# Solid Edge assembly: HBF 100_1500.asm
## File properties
Title: Zylinder
Author: bmolnar
Template: iso assembly.asm
Last saved by: bmolnar
Revision: 64
Application: Solid Edge
Username: bmolnar
Dokumentum tartalom típus: 1
Document Number: HBF 100/1500
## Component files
Kit.par
Profilrohr.par
Kolbenstange_1.par
Mutter.par
Kolbenstange_2.par
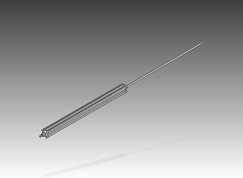
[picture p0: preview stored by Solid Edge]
